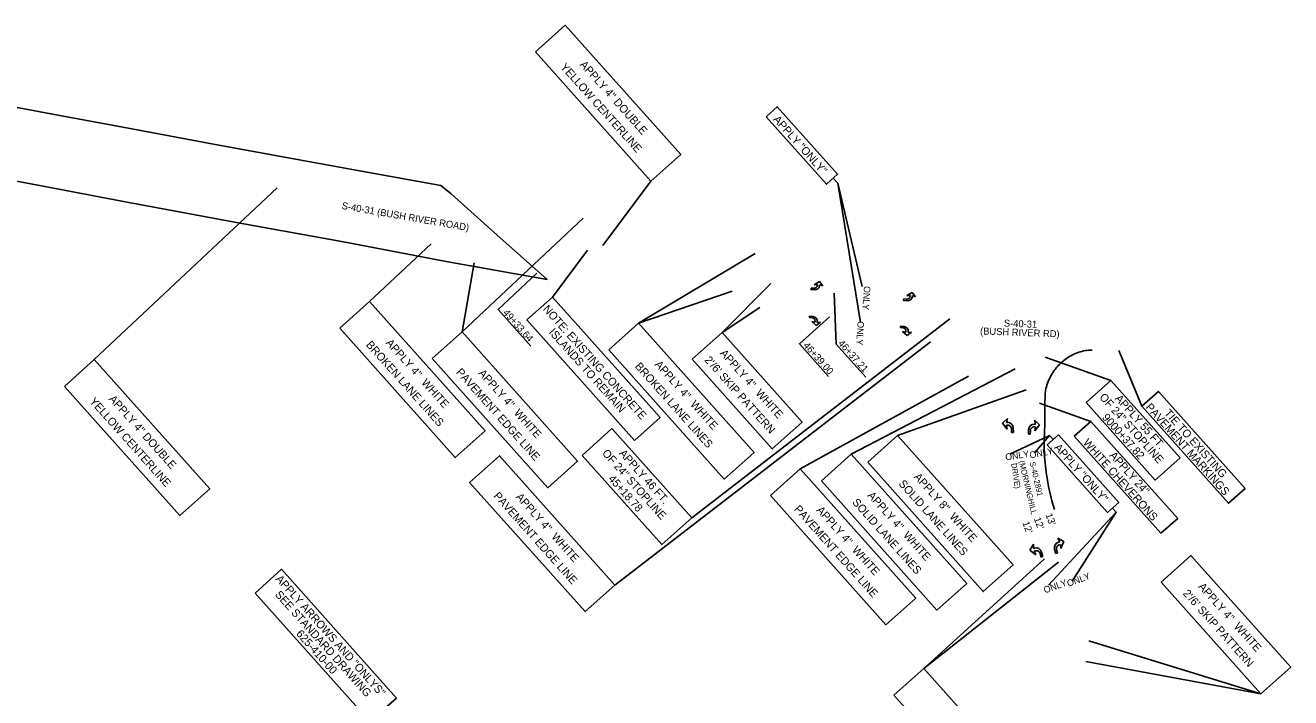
# Model space of a CAD drawing. Extents: x 1966013 to 1974896, y 789499 to 804826.
# Drawn here: x 1968375 to 1969640, y 798921 to 799593 of the extents above; entities that cross this region are included whole.
import ezdxf

# ---------------------------------------------------------------- set-up
doc = ezdxf.new("R2010")
doc.units = 0
for name, color, linetype in [('RD_EX_H2O_BlueLn', 7, 'Continuous'), ('RD_HC_CL_Rel', 7, 'Continuous'), ('RD_HC_Data_Tic_Rel', 7, 'Continuous'), ('RD_HC_TX_Rel_Sta50', 7, 'Continuous'), ('RD_PD_Final_Cl', 7, 'Continuous'), ('RD_PD_MedBWall', 7, 'Continuous'), ('RD_Sketch8', 7, 'Continuous')]:
    doc.layers.add(name, color=color, linetype=linetype)

msp = doc.modelspace()

# ---------------------------------------------------------------- linework, layer by layer
at = {"layer": 'RD_EX_H2O_BlueLn'}
for p, q in [((1968952.8, 799373.1), (1969000.6, 799437.3)), ((1968444.2, 799258.8), (1968627.2, 799430.7)), ((1969212, 799332), (1969187.5, 799435.2)), ((1968933.1, 799400.4), (1968811.9, 799286.5)), ((1968719.4, 799316.8), (1968781, 799374.7)), ((1968902.2, 799321.4), (1968937.2, 799368.3)), ((1968988.3, 799295.2), (1969104.8, 799365)), ((1968811.9, 799286.5), (1968824, 799355.6)), ((1969071.9, 799285.8), (1969120.6, 799334.8)), ((1969081.8, 799327.2), (1968988.3, 799295.2)), ((1969071.9, 799285.8), (1969109.5, 799311)), ((1969041.5, 799100.5), (1969299.5, 799299.6)), ((1968964.8, 799033.4), (1969280.1, 799276.6)), ((1969395, 799261.2), (1969460.6, 799237.9)), ((1969468.5, 799267.8), (1969491.4, 799212.3)), ((1969201, 799164.2), (1969365, 799249.7)), ((1969150, 799149.6), (1969318.3, 799242.4)), ((1969247.4, 799182.9), (1969375.9, 799228.5)), ((1969389.4, 799215.3), (1969440.6, 799197.1)), ((1969399.2, 799183), (1969359.7, 799164.4)), ((1969465.9, 799106.1), (1969421.8, 799037.4)), ((1969273.5, 798949.8), (1969394.2, 799059.6)), ((1969273.5, 798949.8), (1969408.2, 799056.1)), ((1969438.4, 798977.5), (1969610.5, 798924.7)), ((1969435.6, 798957), (1969610.5, 798924.7))]:
    msp.add_line(p, q, dxfattribs=at)
for points in [[(1968885.2, 799566.6), (1969000.6, 799437.3), (1969030.5, 799463.9), (1968915, 799593.2)], [(1969115.9, 799501.8), (1969176.3, 799434.2), (1969187.4, 799444.2), (1969127, 799511.8)], [(1968876.7, 799298.7), (1968984.4, 799178), (1969009.9, 799200.8), (1968902.2, 799321.4)], [(1968689.6, 799290.2), (1968805, 799160.9), (1968834.9, 799187.5), (1968719.4, 799316.8)], [(1968782.1, 799259.9), (1968897.6, 799130.6), (1968927.4, 799157.2), (1968811.9, 799286.5)], [(1968958.5, 799268.6), (1969073.9, 799139.3), (1969103.8, 799165.9), (1968988.3, 799295.2)], [(1969042, 799259.2), (1969122, 799169.6), (1969151.8, 799196.3), (1969071.9, 799285.8)], [(1968414.4, 799232.1), (1968529.8, 799102.8), (1968559.7, 799129.5), (1968444.2, 799258.8)], [(1969435.8, 799215.8), (1969505, 799138.3), (1969529.8, 799160.5), (1969460.6, 799237.9)], [(1969491.4, 799212.3), (1969578.1, 799115.1), (1969594.8, 799130), (1969508.1, 799227.1)], [(1969424, 799182.2), (1969510.7, 799085.1), (1969527.4, 799100), (1969440.6, 799197.1)], [(1968931.9, 799163.1), (1969011.6, 799073.9), (1969041.5, 799100.5), (1968961.8, 799189.8)], [(1969217.6, 799156.2), (1969333, 799026.9), (1969362.9, 799053.6), (1969247.4, 799182.9)], [(1969396.9, 799173.5), (1969457.3, 799105.9), (1969468.5, 799115.9), (1969408.1, 799183.5)], [(1968819.5, 799136.1), (1968935, 799006.8), (1968964.8, 799033.4), (1968849.4, 799162.7)], [(1969171.2, 799137.6), (1969286.6, 799008.3), (1969316.5, 799034.9), (1969201, 799164.2)], [(1969120.2, 799123), (1969235.6, 798993.7), (1969265.5, 799020.3), (1969150, 799149.6)], [(1969510.8, 799036.4), (1969610.5, 798924.7), (1969640.4, 798951.3), (1969540.6, 799063)], [(1968604.9, 799025.4), (1968719.8, 798896.8), (1968746.3, 798920.4), (1968631.4, 799049.1)], [(1969243.7, 798923.2), (1969359.1, 798793.9), (1969388.9, 798820.5), (1969273.5, 798949.8)]]:
    msp.add_lwpolyline(points, close=True, dxfattribs=at)
for points in [[(1969183, 799440.2), (1969187.5, 799435.2), (1969210.2, 799295.9)], [(1968886.7, 799345.3), (1968847.9, 799309.1), (1968880.7, 799272.4)], [(1969183.8, 799325.3), (1969186, 799274.2), (1969215.5, 799241.3)], [(1969179.4, 799301.7), (1969149.2, 799274.7), (1969178.4, 799242.1)], [(1969441.9, 799268.4), (1969441.5, 799268.4), (1969439.9, 799268.4), (1969438.2, 799268.2), (1969436.6, 799268.1), (1969434.9, 799267.8), (1969433.3, 799267.5), (1969431.7, 799267.1), (1969430.1, 799266.7), (1969428.4, 799266.2), (1969426.8, 799265.6), (1969425.2, 799265), (1969423.6, 799264.3), (1969422.1, 799263.5), (1969420.5, 799262.7), (1969419.1, 799261.8), (1969417.6, 799260.9), (1969416.2, 799259.9), (1969414.8, 799258.9), (1969413.5, 799257.8), (1969413, 799257.4), (1969411.7, 799256.4), (1969410.4, 799255.3), (1969409.2, 799254.1), (1969408, 799253), (1969406.9, 799251.7), (1969405.8, 799250.5), (1969404.8, 799249.1), (1969403.8, 799247.8), (1969402.9, 799246.4), (1969402, 799245), (1969401.2, 799243.6), (1969400.3, 799242), (1969399.5, 799240.3), (1969398.7, 799238.6), (1969398, 799236.9), (1969397.3, 799235.2), (1969396.7, 799233.4), (1969396.2, 799231.6), (1969395.7, 799229.9), (1969395.3, 799228), (1969395, 799224.5), (1969394.6, 799213.5), (1969394.5, 799199.7), (1969394.7, 799194.8), (1969394.5, 799191.9), (1969394.2, 799188.1), (1969394.1, 799184.3), (1969394, 799180.6), (1969393.9, 799176.8), (1969393.9, 799173), (1969394, 799169.2), (1969394.2, 799165.5), (1969394.4, 799161.7), (1969396, 799146.2), (1969398.3, 799131.8), (1969401.5, 799117.5), (1969404.3, 799108.8)], [(1969402.9, 799178.9), (1969399.2, 799183), (1969384.3, 799165.6)], [(1969402.9, 799178.9), (1969399.2, 799183)], [(1969462.3, 799110.2), (1969465.9, 799106.1), (1969398.1, 799033.1)], [(1969462.3, 799110.2), (1969465.9, 799106.1)]]:
    msp.add_lwpolyline(points, dxfattribs=at)
at = {"layer": 'RD_HC_Data_Tic_Rel'}
for p, q in [((1969383.1, 799074.1), (1969379.5, 799068.2)), ((1969383.1, 799074.1), (1969379.5, 799068.2)), ((1969383.2, 799070), (1969383.1, 799074.1)), ((1969383.2, 799070), (1969383.1, 799074.1)), ((1969384.2, 799070.3), (1969383.2, 799070)), ((1969384.2, 799070.3), (1969383.2, 799070)), ((1969379.5, 799068.2), (1969385.7, 799063.5)), ((1969379.5, 799068.2), (1969385.7, 799063.5)), ((1969384, 799067.3), (1969385, 799067.6)), ((1969384, 799067.3), (1969385, 799067.6)), ((1969385.7, 799063.5), (1969384, 799067.3)), ((1969385.7, 799063.5), (1969384, 799067.3)), ((1969390, 799064.8), (1969390.9, 799061.4)), ((1969390, 799064.8), (1969390.9, 799061.4)), ((1969390.9, 799061.4), (1969392.6, 799061.9)), ((1969390.9, 799061.4), (1969392.6, 799061.9)), ((1969390.9, 799061.4), (1969390.9, 799061.4)), ((1969390.9, 799061.4), (1969390.9, 799061.4)), ((1969392.6, 799061.9), (1969391.4, 799066.3)), ((1969392.6, 799061.9), (1969391.4, 799066.3))]:
    msp.add_line(p, q, dxfattribs=at)
for centre, radius, start, end in [((1969385.7, 799064.7), 5.88, 16.0959, 104.9385), ((1969385.7, 799064.7), 5.88, 16.0959, 104.9385), ((1969386.1, 799063.8), 3.96, 14.3713, 106.1342), ((1969386.1, 799063.8), 3.96, 14.3713, 106.1342)]:
    msp.add_arc(centre, radius, start, end, dxfattribs=at)
at = {"layer": 'RD_HC_TX_Rel_Sta50'}
for p, q in [((1969169.2, 799337), (1969163.9, 799333.7)), ((1969169.2, 799337), (1969163.9, 799333.7)), ((1969172.6, 799332.6), (1969169.2, 799337)), ((1969172.6, 799332.6), (1969169.2, 799337)), ((1969160.8, 799330.4), (1969160.7, 799329)), ((1969160.8, 799330.4), (1969160.7, 799329)), ((1969160.7, 799329), (1969164.3, 799328.6)), ((1969160.7, 799329), (1969164.3, 799328.6)), ((1969163.6, 799330.2), (1969160.8, 799330.4)), ((1969160.8, 799330.4), (1969160.8, 799330.4)), ((1969163.6, 799330.2), (1969160.8, 799330.4)), ((1969160.8, 799330.4), (1969160.8, 799330.4)), ((1969163.9, 799333.7), (1969167.2, 799333.9)), ((1969163.9, 799333.7), (1969167.2, 799333.9)), ((1969167.2, 799333.9), (1969167.1, 799333)), ((1969167.2, 799333.9), (1969167.1, 799333)), ((1969169.4, 799332.9), (1969169.5, 799333.7)), ((1969169.4, 799332.9), (1969169.5, 799333.7)), ((1969169.5, 799333.7), (1969172.6, 799332.6)), ((1969169.5, 799333.7), (1969172.6, 799332.6)), ((1969261.9, 799326.1), (1969256.6, 799322.8)), ((1969261.9, 799326.1), (1969256.6, 799322.8)), ((1969256.6, 799322.8), (1969259.9, 799323)), ((1969256.6, 799322.8), (1969259.9, 799323)), ((1969259.9, 799323), (1969259.8, 799322.1)), ((1969259.9, 799323), (1969259.8, 799322.1)), ((1969265.3, 799321.7), (1969261.9, 799326.1)), ((1969265.3, 799321.7), (1969261.9, 799326.1)), ((1969262.1, 799321.9), (1969262.2, 799322.8)), ((1969262.1, 799321.9), (1969262.2, 799322.8)), ((1969262.2, 799322.8), (1969265.3, 799321.7)), ((1969262.2, 799322.8), (1969265.3, 799321.7)), ((1969253.5, 799319.5), (1969253.4, 799318)), ((1969253.5, 799319.5), (1969253.4, 799318)), ((1969253.4, 799318), (1969257, 799317.7)), ((1969253.4, 799318), (1969257, 799317.7)), ((1969256.3, 799319.2), (1969253.5, 799319.5)), ((1969253.5, 799319.5), (1969253.5, 799319.5)), ((1969256.3, 799319.2), (1969253.5, 799319.5)), ((1969253.5, 799319.5), (1969253.5, 799319.5)), ((1969159.2, 799300.9), (1969159.4, 799302.4)), ((1969159.2, 799300.9), (1969159.4, 799302.4)), ((1969162, 799300.6), (1969159.2, 799300.9)), ((1969159.2, 799300.9), (1969159.2, 799300.9)), ((1969162, 799300.6), (1969159.2, 799300.9)), ((1969159.2, 799300.9), (1969159.2, 799300.9)), ((1969159.4, 799302.4), (1969163, 799301.9)), ((1969159.4, 799302.4), (1969163, 799301.9)), ((1969166, 799292.8), (1969161.5, 799297.1)), ((1969161.5, 799297.1), (1969164.7, 799296.2)), ((1969166, 799292.8), (1969161.5, 799297.1)), ((1969161.5, 799297.1), (1969164.7, 799296.2)), ((1969164.7, 799296.2), (1969164.8, 799297)), ((1969164.7, 799296.2), (1969164.8, 799297)), ((1969170.3, 799296.4), (1969166, 799292.8)), ((1969170.3, 799296.4), (1969166, 799292.8)), ((1969167.1, 799296.8), (1969167, 799295.9)), ((1969167.1, 799296.8), (1969167, 799295.9)), ((1969167, 799295.9), (1969170.3, 799296.4)), ((1969167, 799295.9), (1969170.3, 799296.4)), ((1969250.1, 799291), (1969250.2, 799292.4)), ((1969250.1, 799291), (1969250.2, 799292.4)), ((1969252.8, 799290.6), (1969250.1, 799291)), ((1969250.1, 799291), (1969250.1, 799291)), ((1969252.8, 799290.6), (1969250.1, 799291)), ((1969250.1, 799291), (1969250.1, 799291)), ((1969250.2, 799292.4), (1969253.9, 799291.9)), ((1969250.2, 799292.4), (1969253.9, 799291.9)), ((1969256.9, 799282.8), (1969252.4, 799287.1)), ((1969252.4, 799287.1), (1969255.6, 799286.2)), ((1969256.9, 799282.8), (1969252.4, 799287.1)), ((1969252.4, 799287.1), (1969255.6, 799286.2)), ((1969255.6, 799286.2), (1969255.7, 799287.1)), ((1969255.6, 799286.2), (1969255.7, 799287.1)), ((1969261.1, 799286.4), (1969256.9, 799282.8)), ((1969261.1, 799286.4), (1969256.9, 799282.8)), ((1969258, 799286.8), (1969257.9, 799285.9)), ((1969258, 799286.8), (1969257.9, 799285.9)), ((1969257.9, 799285.9), (1969261.1, 799286.4)), ((1969257.9, 799285.9), (1969261.1, 799286.4)), ((1969357.3, 799200), (1969352.3, 799195.3)), ((1969357.3, 799200), (1969352.3, 799195.3)), ((1969352.3, 799195.3), (1969356.9, 799189.2)), ((1969352.3, 799195.3), (1969356.9, 799189.2)), ((1969356.3, 799196.1), (1969357.3, 799200)), ((1969356.3, 799196.1), (1969357.3, 799200)), ((1969357.3, 799196.1), (1969356.3, 799196.1)), ((1969357.3, 799196.1), (1969356.3, 799196.1)), ((1969385.3, 799194.3), (1969384.4, 799198.3)), ((1969384.4, 799198.3), (1969389.3, 799193.5)), ((1969384.4, 799198.3), (1969389.3, 799193.5)), ((1969385.3, 799194.3), (1969384.4, 799198.3)), ((1969356.9, 799189.2), (1969356.3, 799193.2)), ((1969356.3, 799193.2), (1969357.3, 799193.2)), ((1969356.9, 799189.2), (1969356.3, 799193.2)), ((1969356.3, 799193.2), (1969357.3, 799193.2)), ((1969361.3, 799189.2), (1969361.3, 799185.8)), ((1969361.3, 799189.2), (1969361.3, 799185.8)), ((1969361.3, 799185.8), (1969361.3, 799185.8)), ((1969361.3, 799185.8), (1969363.1, 799185.8)), ((1969361.3, 799185.8), (1969361.3, 799185.8)), ((1969361.3, 799185.8), (1969363.1, 799185.8)), ((1969363.1, 799185.8), (1969363, 799190.3)), ((1969363.1, 799185.8), (1969363, 799190.3)), ((1969378.2, 799184.2), (1969378.4, 799188.7)), ((1969378.2, 799184.2), (1969378.4, 799188.7)), ((1969380, 799184.2), (1969378.2, 799184.2)), ((1969380, 799184.2), (1969378.2, 799184.2)), ((1969380.1, 799187.6), (1969380, 799184.2)), ((1969380.1, 799187.6), (1969380, 799184.2)), ((1969380, 799184.2), (1969380, 799184.2)), ((1969380, 799184.2), (1969380, 799184.2)), ((1969384.2, 799194.4), (1969385.3, 799194.3)), ((1969384.2, 799194.4), (1969385.3, 799194.3)), ((1969385.2, 799191.5), (1969384.2, 799191.5)), ((1969385.2, 799191.5), (1969384.2, 799191.5)), ((1969389.3, 799193.5), (1969384.5, 799187.5)), ((1969389.3, 799193.5), (1969384.5, 799187.5)), ((1969384.5, 799187.5), (1969385.2, 799191.5)), ((1969384.5, 799187.5), (1969385.2, 799191.5)), ((1969405.4, 799065), (1969404.3, 799069.3)), ((1969405.4, 799065), (1969404.3, 799069.3)), ((1969406.3, 799068.7), (1969407.1, 799065.4)), ((1969406.3, 799068.7), (1969407.1, 799065.4)), ((1969409.4, 799076.7), (1969407.4, 799080.2)), ((1969407.4, 799080.2), (1969413.4, 799076.9)), ((1969407.4, 799080.2), (1969413.4, 799076.9)), ((1969409.4, 799076.7), (1969407.4, 799080.2)), ((1969408.4, 799076.4), (1969409.4, 799076.7)), ((1969408.4, 799076.4), (1969409.4, 799076.7)), ((1969410.1, 799073.9), (1969409.1, 799073.6)), ((1969410.1, 799073.9), (1969409.1, 799073.6)), ((1969410.5, 799069.8), (1969410.1, 799073.9)), ((1969410.5, 799069.8), (1969410.1, 799073.9)), ((1969413.4, 799076.9), (1969410.5, 799069.8)), ((1969413.4, 799076.9), (1969410.5, 799069.8)), ((1969407.1, 799065.4), (1969405.4, 799065)), ((1969407.1, 799065.4), (1969405.4, 799065)), ((1969407.1, 799065.4), (1969407.1, 799065.4)), ((1969407.1, 799065.4), (1969407.1, 799065.4))]:
    msp.add_line(p, q, dxfattribs=at)
for centre, radius, start, end in [((1969164, 799333.3), 3.18, 263.4485, 355.2113), ((1969164, 799333.3), 3.18, 263.4485, 355.2113), ((1969164.7, 799333.3), 4.72, 265.173, 354.0156), ((1969164.7, 799333.3), 4.72, 265.173, 354.0156), ((1969256.7, 799322.4), 3.18, 263.4485, 355.2113), ((1969256.7, 799322.4), 3.18, 263.4485, 355.2113), ((1969257.4, 799322.4), 4.72, 265.173, 354.0156), ((1969257.4, 799322.4), 4.72, 265.173, 354.0156), ((1969161.7, 799297.4), 3.18, 352.9759, 84.7387), ((1969161.7, 799297.4), 3.18, 352.9759, 84.7387), ((1969162.4, 799297.2), 4.72, 354.1716, 83.0141), ((1969162.4, 799297.2), 4.72, 354.1716, 83.0141), ((1969252.5, 799287.5), 3.18, 352.9759, 84.7387), ((1969252.5, 799287.5), 3.18, 352.9759, 84.7387), ((1969253.3, 799287.3), 4.72, 354.1716, 83.0141), ((1969253.3, 799287.3), 4.72, 354.1716, 83.0141), ((1969357.2, 799190.3), 5.82, 0.2257, 89.0682), ((1969357.2, 799190.3), 5.82, 0.2257, 89.0682), ((1969357.4, 799189.3), 3.92, 358.5011, 90.2639), ((1969357.4, 799189.3), 3.92, 358.5011, 90.2639), ((1969384.2, 799188.6), 5.82, 89.4501, 178.2927), ((1969384.2, 799188.6), 5.82, 89.4501, 178.2927), ((1969384, 799187.6), 3.92, 88.2544, 180.0173), ((1969384, 799187.6), 3.92, 88.2544, 180.0173), ((1969409.9, 799070.8), 5.82, 105.4075, 194.2501), ((1969409.9, 799070.8), 5.82, 105.4075, 194.2501), ((1969410, 799069.8), 3.92, 104.2118, 195.9747), ((1969410, 799069.8), 3.92, 104.2118, 195.9747)]:
    msp.add_arc(centre, radius, start, end, dxfattribs=at)
at = {"layer": 'RD_Sketch8'}
msp.add_lwpolyline([(1968850, 799380.7), (1968896.9, 799339), (1968795.9, 799357), (1968693.3, 799376.5), (1968591.8, 799395.1), (1968478.9, 799416.1), (1968380.9, 799434.5), (1968257.6, 799457.4), (1968238.2, 799483.9), (1968200.9, 799534.9), (1968194.3, 799543.7), (1968199.1, 799542.8), (1968242.6, 799534.3), (1968326.2, 799518.6), (1968400.9, 799504.7), (1968481.9, 799489.5), (1968563.3, 799474.4), (1968649.2, 799458.7), (1968711.2, 799447.3), (1968790.8, 799433), (1968801.1, 799424.6), (1968850, 799380.7)], dxfattribs=at)

# ---------------------------------------------------------------- texts
at = {"layer": 'RD_EX_H2O_BlueLn'}
for s, height, rotation, p in [('YELLOW CENTERLINE', 7.999, 311.7606, (1968909.7, 799551.1)), ("APPLY 4'' DOUBLE", 7.999, 311.7606, (1968929.1, 799553.5)), ('APPLY "ONLY"', 7.999, 311.7469, (1969122.4, 799498.7)), ('NOTE: EXISTING CONCRETE', 8, 311.7605, (1968892.2, 799309)), ('49+33.64', 7, 311.7606, (1968852.4, 799305.3)), ('ISLANDS TO REMAIN', 8, 311.7605, (1968898.1, 799285.8)), ('BROKEN LANE LINES', 8, 311.7606, (1968715.3, 799273.3)), ("APPLY 4''  WHITE", 8, 311.7606, (1968735.1, 799275.2)), ('46+39.00', 7, 311.7606, (1969152.6, 799272.6)), ('46+37.21', 7, 311.7606, (1969187.4, 799274.8)), ("2'/6' SKIP PATTERN", 7.999, 311.7608, (1969053.8, 799258)), ("APPLY 4''  WHITE", 7.999, 311.7608, (1969069.2, 799264.8)), ('PAVEMENT EDGE LINE', 8, 311.7606, (1968805.4, 799245.8)), ("APPLY 4''  WHITE", 8, 311.7606, (1968827.7, 799244.9)), ('BROKEN LANE LINES', 8, 311.7606, (1968984.2, 799251.7)), ("APPLY 4''  WHITE", 8, 311.7606, (1969004, 799253.6)), ('YELLOW CENTERLINE', 7.999, 311.7606, (1968438.9, 799216.7)), ("APPLY 4'' DOUBLE", 7.999, 311.7606, (1968458.2, 799219.1)), ('OF 24" STOPLINE', 7.999, 311.7606, (1969448.5, 799220.9)), ('APPLY 55 FT.', 8, 311.7606, (1969464.1, 799219.5)), ('PAVEMENT MARKINGS', 8, 311.7606, (1969494.8, 799210.9)), ('TIE TO EXISTING', 8, 311.7606, (1969513.4, 799204.9)), ('9000+37.82', 8, 311.7606, (1969451.3, 799200.6)), ('APPLY "ONLY"', 7.999, 311.7503, (1969403.4, 799170.5)), ('WHITE CHEVERONS', 8, 311.7606, (1969432.2, 799175.3)), ('OF 24" STOPLINE', 7.999, 311.7606, (1968951.4, 799164.9)), ('APPLY 46 FT.', 7.999, 311.7606, (1968968.3, 799164.7)), ('APPLY 24"', 8, 311.7606, (1969458.6, 799162.6)), ("APPLY 8''  WHITE", 8, 311.7606, (1969263.1, 799141.2)), ('45+18.78', 8, 311.7606, (1968957.5, 799139.2)), ('SOLID LANE LINES', 8, 311.7606, (1969247.9, 799134.3)), ('PAVEMENT EDGE LINE', 8, 311.7606, (1968842.8, 799122.1)), ("APPLY 4''  WHITE", 8, 311.7606, (1968865.1, 799121.1)), ('SOLID LANE LINES', 8, 311.7606, (1969201.5, 799115.7)), ("APPLY 4''  WHITE", 8, 311.7606, (1969216.8, 799122.6)), ('PAVEMENT EDGE LINE', 8, 311.7606, (1969143.4, 799108.9)), ("APPLY 4''  WHITE", 8, 311.7606, (1969165.7, 799107.9)), ('APPLY ARROWS AND "ONLYS"', 8, 311.7606, (1968624.9, 799039.1)), ("APPLY 4''  WHITE", 7.999, 311.7608, (1969547.4, 799031.4)), ('SEE STANDARD DRAWING', 8, 311.7606, (1968624.3, 799023.5)), ("2'/6' SKIP PATTERN", 7.999, 311.7608, (1969532.1, 799024.6)), ('625-410-00 ', 8, 311.7606, (1968645.4, 798984.3))]:
    msp.add_text(s, height=height, rotation=rotation, dxfattribs=at).set_placement(p)
at = {"layer": 'RD_HC_CL_Rel'}
for s, p in [("12'", (1969372, 799095.7)), ("12'", (1969383.5, 799099.8)), ("13'", (1969395.1, 799103.7))]:
    msp.add_text(s, height=7, rotation=290.0075, dxfattribs=at).set_placement(p)
at = {"layer": 'RD_HC_TX_Rel_Sta50'}
for rotation, p in [(265.9305, (1969213.8, 799332.6)), (265.9305, (1969207.5, 799297.4)), (10.7203, (1969379.9, 799160)), (8.1213, (1969355.5, 799158)), (19.9791, (1969418.1, 799031.6)), (19.9791, (1969394.8, 799025))]:
    msp.add_text('ONLY', height=6.56, rotation=rotation, dxfattribs=at).set_placement(p)
at = {"layer": 'RD_PD_Final_Cl'}
for s, rotation, p in [('(MORNINGHILL', 283.1713, (1969368.6, 799157.1)), ('DRIVE)', 278.4271, (1969360.9, 799154.9)), ('S-40-2891', 283.2461, (1969379.3, 799156))]:
    msp.add_text(s, height=5.67, rotation=rotation, dxfattribs=at).set_placement(p)
at = {"layer": 'RD_PD_MedBWall'}
for s, rotation, p in [('S-40-31 (BUSH RIVER ROAD)', 350.0747, (1968691.2, 799409.6)), ('S-40-31', 357.8018, (1969353.5, 799291.9)), ('(BUSH RIVER RD)', 357.8018, (1969329.7, 799284.1))]:
    msp.add_text(s, height=7, rotation=rotation, dxfattribs=at).set_placement(p)

doc.saveas('drawing.dxf')
